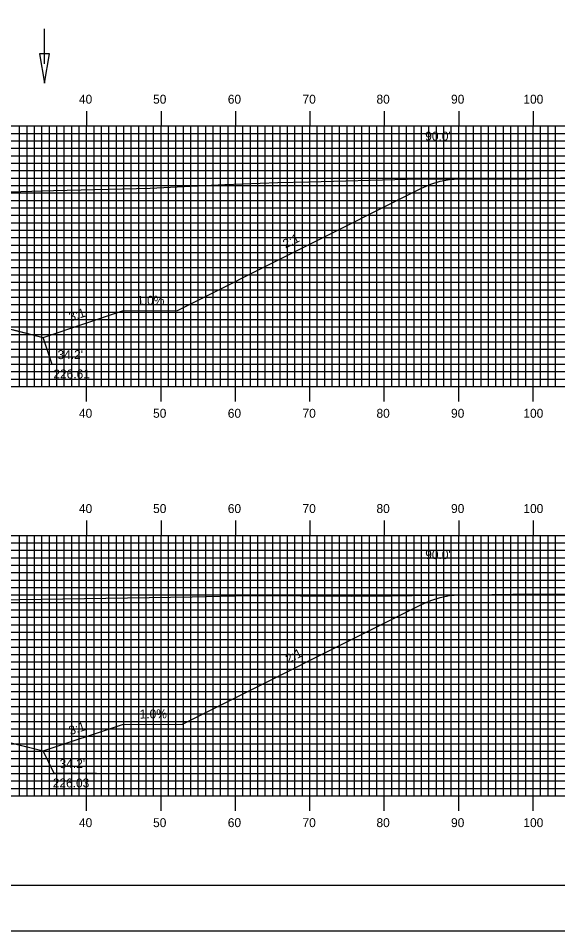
# Model space of a CAD drawing. Extents: x 1817670 to 1818013, y 442591 to 442811.
# Drawn here: x 1817866.4 to 1817938.9, y 442590.5 to 442713.1 of the extents above; entities that cross this region are included whole.
import ezdxf

# ---------------------------------------------------------------- set-up
doc = ezdxf.new("R2010")
doc.units = 0
for name, color, linetype in [('ANNOTATION', 7, 'Continuous'), ('BORDER', 7, 'Continuous'), ('D_Drainage_Ditch_Line', 7, 'Continuous'), ('D_Roadway_Centerline', 7, 'Continuous'), ('D_Roadway_SlopeLines', 7, 'Continuous'), ('D_Text_Standard', 7, 'Continuous'), ('H_V ANNOTATION', 7, 'Continuous'), ('MAJOR', 7, 'Continuous'), ('MINOR', 7, 'Continuous'), ('PLOT BOUNDARY', 7, 'Continuous'), ('S_Roadway_Centerline', 7, 'Continuous')]:
    doc.layers.add(name, color=color, linetype=linetype)

msp = doc.modelspace()

# ---------------------------------------------------------------- linework, layer by layer
at = {"layer": 'ANNOTATION'}
for points in [[(1817876.65, 442666.62), (1817870.96, 442666.62), (1817869.79, 442670.27)], [(1817876.94, 442611.67), (1817871.25, 442611.67), (1817869.79, 442614.7)]]:
    msp.add_lwpolyline(points, dxfattribs=at)
at = {"layer": 'BORDER'}
msp.add_lwpolyline([(1817686.01, 442596.67), (1818006.01, 442596.67), (1818006.01, 442806.67), (1817686.01, 442806.67)], close=True, dxfattribs=at)
at = {"layer": 'D_Drainage_Ditch_Line'}
msp.add_line((1817869.95, 442707.03), (1817869.95, 442711.73), dxfattribs=at)
msp.add_lwpolyline([(1817870.61, 442708.35), (1817869.29, 442708.35), (1817869.95, 442704.41)], close=True, dxfattribs=at)
at = {"layer": 'D_Roadway_Centerline'}
for points in [[(1817745.61, 442681.47), (1817746.86, 442681.54), (1817748.11, 442681.41), (1817749.36, 442681.08), (1817750.61, 442680.56), (1817763.55, 442674.09), (1817790.81, 442673.82), (1817801.44, 442670.27), (1817805.44, 442671.27), (1817815.61, 442673.82), (1817823.61, 442674.14), (1817835.61, 442674.38), (1817847.61, 442674.14), (1817855.61, 442673.82), (1817865.79, 442671.27), (1817869.79, 442670.27), (1817880.42, 442673.82), (1817887.8, 442673.89), (1817920.61, 442690.3), (1817921.86, 442690.85), (1817923.11, 442691.24), (1817924.36, 442691.47), (1817925.61, 442691.56)], [(1817745.61, 442627.29), (1817746.86, 442627.3), (1817748.11, 442627.13), (1817749.36, 442626.77), (1817750.61, 442626.24), (1817766.12, 442618.49), (1817790.81, 442618.24), (1817801.44, 442614.7), (1817805.44, 442615.7), (1817815.61, 442618.24), (1817823.61, 442618.56), (1817835.61, 442618.8), (1817847.61, 442618.56), (1817855.61, 442618.24), (1817865.79, 442615.7), (1817869.79, 442614.7), (1817880.42, 442618.24), (1817888.49, 442618.32), (1817920.61, 442634.38), (1817921.86, 442634.93), (1817923.11, 442635.33), (1817924.36, 442635.58), (1817925.61, 442635.67)]]:
    msp.add_lwpolyline(points, dxfattribs=at)
at = {"layer": 'D_Roadway_SlopeLines'}
for points in [[(1817880.42, 442673.82), (1817887.8, 442673.89), (1817920.61, 442690.3), (1817921.86, 442690.85), (1817923.11, 442691.24), (1817924.36, 442691.47), (1817925.61, 442691.56)], [(1817855.61, 442673.82), (1817869.79, 442670.27)], [(1817869.79, 442670.27), (1817880.42, 442673.82)], [(1817880.42, 442618.24), (1817888.49, 442618.32), (1817920.61, 442634.38), (1817921.86, 442634.93), (1817923.11, 442635.33), (1817924.36, 442635.58), (1817925.61, 442635.67)], [(1817855.61, 442618.24), (1817869.79, 442614.7)], [(1817869.79, 442614.7), (1817880.42, 442618.24)]]:
    msp.add_lwpolyline(points, dxfattribs=at)
at = {"layer": 'MAJOR'}
for p, q in [((1817875.61, 442700.67), (1817875.61, 442698.67)), ((1817885.61, 442700.67), (1817885.61, 442698.67)), ((1817895.61, 442700.67), (1817895.61, 442698.67)), ((1817905.61, 442700.67), (1817905.61, 442698.67)), ((1817915.61, 442700.67), (1817915.61, 442698.67)), ((1817925.61, 442700.67), (1817925.61, 442698.67)), ((1817935.61, 442700.67), (1817935.61, 442698.67)), ((1817695.61, 442698.67), (1817975.61, 442698.67)), ((1817695.61, 442698.67), (1817975.61, 442698.67)), ((1817875.61, 442663.67), (1817875.61, 442698.67)), ((1817885.61, 442663.67), (1817885.61, 442698.67)), ((1817895.61, 442663.67), (1817895.61, 442698.67)), ((1817905.61, 442663.67), (1817905.61, 442698.67)), ((1817915.61, 442663.67), (1817915.61, 442698.67)), ((1817925.61, 442663.67), (1817925.61, 442698.67)), ((1817935.61, 442663.67), (1817935.61, 442698.67)), ((1817695.61, 442693.67), (1817975.61, 442693.67)), ((1817695.61, 442688.67), (1817975.61, 442688.67)), ((1817695.61, 442683.67), (1817975.61, 442683.67)), ((1817695.61, 442678.67), (1817975.61, 442678.67)), ((1817695.61, 442673.67), (1817975.61, 442673.67)), ((1817695.61, 442668.67), (1817975.61, 442668.67)), ((1817695.61, 442663.67), (1817975.61, 442663.67)), ((1817695.61, 442663.67), (1817975.61, 442663.67)), ((1817875.61, 442661.66), (1817875.61, 442663.67)), ((1817885.61, 442661.66), (1817885.61, 442663.67)), ((1817895.61, 442661.66), (1817895.61, 442663.67)), ((1817905.61, 442661.66), (1817905.61, 442663.67)), ((1817915.61, 442661.66), (1817915.61, 442663.67)), ((1817925.61, 442661.66), (1817925.61, 442663.67)), ((1817935.61, 442661.66), (1817935.61, 442663.67)), ((1817875.61, 442645.67), (1817875.61, 442643.67)), ((1817885.61, 442645.67), (1817885.61, 442643.67)), ((1817895.61, 442645.67), (1817895.61, 442643.67)), ((1817905.61, 442645.67), (1817905.61, 442643.67)), ((1817915.61, 442645.67), (1817915.61, 442643.67)), ((1817925.61, 442645.67), (1817925.61, 442643.67)), ((1817935.61, 442645.67), (1817935.61, 442643.67)), ((1817695.61, 442643.67), (1817975.61, 442643.67)), ((1817695.61, 442643.67), (1817975.61, 442643.67)), ((1817875.61, 442608.67), (1817875.61, 442643.67)), ((1817885.61, 442608.67), (1817885.61, 442643.67)), ((1817895.61, 442608.67), (1817895.61, 442643.67)), ((1817905.61, 442608.67), (1817905.61, 442643.67)), ((1817915.61, 442608.67), (1817915.61, 442643.67)), ((1817925.61, 442608.67), (1817925.61, 442643.67)), ((1817935.61, 442608.67), (1817935.61, 442643.67)), ((1817695.61, 442638.67), (1817975.61, 442638.67)), ((1817695.61, 442633.67), (1817975.61, 442633.67)), ((1817695.61, 442628.67), (1817975.61, 442628.67)), ((1817695.61, 442623.67), (1817975.61, 442623.67)), ((1817695.61, 442618.67), (1817975.61, 442618.67)), ((1817695.61, 442613.67), (1817975.61, 442613.67)), ((1817695.61, 442608.67), (1817975.61, 442608.67)), ((1817695.61, 442608.67), (1817975.61, 442608.67)), ((1817875.61, 442606.66), (1817875.61, 442608.67)), ((1817885.61, 442606.66), (1817885.61, 442608.67)), ((1817895.61, 442606.66), (1817895.61, 442608.67)), ((1817905.61, 442606.66), (1817905.61, 442608.67)), ((1817915.61, 442606.66), (1817915.61, 442608.67)), ((1817925.61, 442606.66), (1817925.61, 442608.67)), ((1817935.61, 442606.66), (1817935.61, 442608.67))]:
    msp.add_line(p, q, dxfattribs=at)
at = {"layer": 'MINOR'}
for p, q in [((1817866.61, 442663.67), (1817866.61, 442698.67)), ((1817867.61, 442663.67), (1817867.61, 442698.67)), ((1817868.61, 442663.67), (1817868.61, 442698.67)), ((1817869.61, 442663.67), (1817869.61, 442698.67)), ((1817870.61, 442663.67), (1817870.61, 442698.67)), ((1817871.61, 442663.67), (1817871.61, 442698.67)), ((1817872.61, 442663.67), (1817872.61, 442698.67)), ((1817873.61, 442663.67), (1817873.61, 442698.67)), ((1817874.61, 442663.67), (1817874.61, 442698.67)), ((1817876.61, 442663.67), (1817876.61, 442698.67)), ((1817877.61, 442663.67), (1817877.61, 442698.67)), ((1817878.61, 442663.67), (1817878.61, 442698.67)), ((1817879.61, 442663.67), (1817879.61, 442698.67)), ((1817880.61, 442663.67), (1817880.61, 442698.67)), ((1817881.61, 442663.67), (1817881.61, 442698.67)), ((1817882.61, 442663.67), (1817882.61, 442698.67)), ((1817883.61, 442663.67), (1817883.61, 442698.67)), ((1817884.61, 442663.67), (1817884.61, 442698.67)), ((1817886.61, 442663.67), (1817886.61, 442698.67)), ((1817887.61, 442663.67), (1817887.61, 442698.67)), ((1817888.61, 442663.67), (1817888.61, 442698.67)), ((1817889.61, 442663.67), (1817889.61, 442698.67)), ((1817890.61, 442663.67), (1817890.61, 442698.67)), ((1817891.61, 442663.67), (1817891.61, 442698.67)), ((1817892.61, 442663.67), (1817892.61, 442698.67)), ((1817893.61, 442663.67), (1817893.61, 442698.67)), ((1817894.61, 442663.67), (1817894.61, 442698.67)), ((1817896.61, 442663.67), (1817896.61, 442698.67)), ((1817897.61, 442663.67), (1817897.61, 442698.67)), ((1817898.61, 442663.67), (1817898.61, 442698.67)), ((1817899.61, 442663.67), (1817899.61, 442698.67)), ((1817900.61, 442663.67), (1817900.61, 442698.67)), ((1817901.61, 442663.67), (1817901.61, 442698.67)), ((1817902.61, 442663.67), (1817902.61, 442698.67)), ((1817903.61, 442663.67), (1817903.61, 442698.67)), ((1817904.61, 442663.67), (1817904.61, 442698.67)), ((1817906.61, 442663.67), (1817906.61, 442698.67)), ((1817907.61, 442663.67), (1817907.61, 442698.67)), ((1817908.61, 442663.67), (1817908.61, 442698.67)), ((1817909.61, 442663.67), (1817909.61, 442698.67)), ((1817910.61, 442663.67), (1817910.61, 442698.67)), ((1817911.61, 442663.67), (1817911.61, 442698.67)), ((1817912.61, 442663.67), (1817912.61, 442698.67)), ((1817913.61, 442663.67), (1817913.61, 442698.67)), ((1817914.61, 442663.67), (1817914.61, 442698.67)), ((1817916.61, 442663.67), (1817916.61, 442698.67)), ((1817917.61, 442663.67), (1817917.61, 442698.67)), ((1817918.61, 442663.67), (1817918.61, 442698.67)), ((1817919.61, 442663.67), (1817919.61, 442698.67)), ((1817920.61, 442663.67), (1817920.61, 442698.67)), ((1817921.61, 442663.67), (1817921.61, 442698.67)), ((1817922.61, 442663.67), (1817922.61, 442698.67)), ((1817923.61, 442663.67), (1817923.61, 442698.67)), ((1817924.61, 442663.67), (1817924.61, 442698.67)), ((1817926.61, 442663.67), (1817926.61, 442698.67)), ((1817927.61, 442663.67), (1817927.61, 442698.67)), ((1817928.61, 442663.67), (1817928.61, 442698.67)), ((1817929.61, 442663.67), (1817929.61, 442698.67)), ((1817930.61, 442663.67), (1817930.61, 442698.67)), ((1817931.61, 442663.67), (1817931.61, 442698.67)), ((1817932.61, 442663.67), (1817932.61, 442698.67)), ((1817933.61, 442663.67), (1817933.61, 442698.67)), ((1817934.61, 442663.67), (1817934.61, 442698.67)), ((1817936.61, 442663.67), (1817936.61, 442698.67)), ((1817937.61, 442663.67), (1817937.61, 442698.67)), ((1817938.61, 442663.67), (1817938.61, 442698.67)), ((1817695.61, 442697.67), (1817975.61, 442697.67)), ((1817695.61, 442696.67), (1817975.61, 442696.67)), ((1817695.61, 442695.67), (1817975.61, 442695.67)), ((1817695.61, 442694.67), (1817975.61, 442694.67)), ((1817695.61, 442692.67), (1817975.61, 442692.67)), ((1817695.61, 442691.67), (1817975.61, 442691.67)), ((1817695.61, 442690.67), (1817975.61, 442690.67)), ((1817695.61, 442689.67), (1817975.61, 442689.67)), ((1817695.61, 442687.67), (1817975.61, 442687.67)), ((1817695.61, 442686.67), (1817975.61, 442686.67)), ((1817695.61, 442685.67), (1817975.61, 442685.67)), ((1817695.61, 442684.67), (1817975.61, 442684.67)), ((1817695.61, 442682.67), (1817975.61, 442682.67)), ((1817695.61, 442681.67), (1817975.61, 442681.67)), ((1817695.61, 442680.67), (1817975.61, 442680.67)), ((1817695.61, 442679.67), (1817975.61, 442679.67)), ((1817695.61, 442677.67), (1817975.61, 442677.67)), ((1817695.61, 442676.67), (1817975.61, 442676.67)), ((1817695.61, 442675.67), (1817975.61, 442675.67)), ((1817695.61, 442674.67), (1817975.61, 442674.67)), ((1817695.61, 442672.67), (1817975.61, 442672.67)), ((1817695.61, 442671.67), (1817975.61, 442671.67)), ((1817695.61, 442670.67), (1817975.61, 442670.67)), ((1817695.61, 442669.67), (1817975.61, 442669.67)), ((1817695.61, 442667.67), (1817975.61, 442667.67)), ((1817695.61, 442666.67), (1817975.61, 442666.67)), ((1817695.61, 442665.67), (1817975.61, 442665.67)), ((1817695.61, 442664.67), (1817975.61, 442664.67)), ((1817866.61, 442608.67), (1817866.61, 442643.67)), ((1817867.61, 442608.67), (1817867.61, 442643.67)), ((1817868.61, 442608.67), (1817868.61, 442643.67)), ((1817869.61, 442608.67), (1817869.61, 442643.67)), ((1817870.61, 442608.67), (1817870.61, 442643.67)), ((1817871.61, 442608.67), (1817871.61, 442643.67)), ((1817872.61, 442608.67), (1817872.61, 442643.67)), ((1817873.61, 442608.67), (1817873.61, 442643.67)), ((1817874.61, 442608.67), (1817874.61, 442643.67)), ((1817876.61, 442608.67), (1817876.61, 442643.67)), ((1817877.61, 442608.67), (1817877.61, 442643.67)), ((1817878.61, 442608.67), (1817878.61, 442643.67)), ((1817879.61, 442608.67), (1817879.61, 442643.67)), ((1817880.61, 442608.67), (1817880.61, 442643.67)), ((1817881.61, 442608.67), (1817881.61, 442643.67)), ((1817882.61, 442608.67), (1817882.61, 442643.67)), ((1817883.61, 442608.67), (1817883.61, 442643.67)), ((1817884.61, 442608.67), (1817884.61, 442643.67)), ((1817886.61, 442608.67), (1817886.61, 442643.67)), ((1817887.61, 442608.67), (1817887.61, 442643.67)), ((1817888.61, 442608.67), (1817888.61, 442643.67)), ((1817889.61, 442608.67), (1817889.61, 442643.67)), ((1817890.61, 442608.67), (1817890.61, 442643.67)), ((1817891.61, 442608.67), (1817891.61, 442643.67)), ((1817892.61, 442608.67), (1817892.61, 442643.67)), ((1817893.61, 442608.67), (1817893.61, 442643.67)), ((1817894.61, 442608.67), (1817894.61, 442643.67)), ((1817896.61, 442608.67), (1817896.61, 442643.67)), ((1817897.61, 442608.67), (1817897.61, 442643.67)), ((1817898.61, 442608.67), (1817898.61, 442643.67)), ((1817899.61, 442608.67), (1817899.61, 442643.67)), ((1817900.61, 442608.67), (1817900.61, 442643.67)), ((1817901.61, 442608.67), (1817901.61, 442643.67)), ((1817902.61, 442608.67), (1817902.61, 442643.67)), ((1817903.61, 442608.67), (1817903.61, 442643.67)), ((1817904.61, 442608.67), (1817904.61, 442643.67)), ((1817906.61, 442608.67), (1817906.61, 442643.67)), ((1817907.61, 442608.67), (1817907.61, 442643.67)), ((1817908.61, 442608.67), (1817908.61, 442643.67)), ((1817909.61, 442608.67), (1817909.61, 442643.67)), ((1817910.61, 442608.67), (1817910.61, 442643.67)), ((1817911.61, 442608.67), (1817911.61, 442643.67)), ((1817912.61, 442608.67), (1817912.61, 442643.67)), ((1817913.61, 442608.67), (1817913.61, 442643.67)), ((1817914.61, 442608.67), (1817914.61, 442643.67)), ((1817916.61, 442608.67), (1817916.61, 442643.67)), ((1817917.61, 442608.67), (1817917.61, 442643.67)), ((1817918.61, 442608.67), (1817918.61, 442643.67)), ((1817919.61, 442608.67), (1817919.61, 442643.67)), ((1817920.61, 442608.67), (1817920.61, 442643.67)), ((1817921.61, 442608.67), (1817921.61, 442643.67)), ((1817922.61, 442608.67), (1817922.61, 442643.67)), ((1817923.61, 442608.67), (1817923.61, 442643.67)), ((1817924.61, 442608.67), (1817924.61, 442643.67)), ((1817926.61, 442608.67), (1817926.61, 442643.67)), ((1817927.61, 442608.67), (1817927.61, 442643.67)), ((1817928.61, 442608.67), (1817928.61, 442643.67)), ((1817929.61, 442608.67), (1817929.61, 442643.67)), ((1817930.61, 442608.67), (1817930.61, 442643.67)), ((1817931.61, 442608.67), (1817931.61, 442643.67)), ((1817932.61, 442608.67), (1817932.61, 442643.67)), ((1817933.61, 442608.67), (1817933.61, 442643.67)), ((1817934.61, 442608.67), (1817934.61, 442643.67)), ((1817936.61, 442608.67), (1817936.61, 442643.67)), ((1817937.61, 442608.67), (1817937.61, 442643.67)), ((1817938.61, 442608.67), (1817938.61, 442643.67)), ((1817695.61, 442642.67), (1817975.61, 442642.67)), ((1817695.61, 442641.67), (1817975.61, 442641.67)), ((1817695.61, 442640.67), (1817975.61, 442640.67)), ((1817695.61, 442639.67), (1817975.61, 442639.67)), ((1817695.61, 442637.67), (1817975.61, 442637.67)), ((1817695.61, 442636.67), (1817975.61, 442636.67)), ((1817695.61, 442635.67), (1817975.61, 442635.67)), ((1817695.61, 442634.67), (1817975.61, 442634.67)), ((1817695.61, 442632.67), (1817975.61, 442632.67)), ((1817695.61, 442631.67), (1817975.61, 442631.67)), ((1817695.61, 442630.67), (1817975.61, 442630.67)), ((1817695.61, 442629.67), (1817975.61, 442629.67)), ((1817695.61, 442627.67), (1817975.61, 442627.67)), ((1817695.61, 442626.67), (1817975.61, 442626.67)), ((1817695.61, 442625.67), (1817975.61, 442625.67)), ((1817695.61, 442624.67), (1817975.61, 442624.67)), ((1817695.61, 442622.67), (1817975.61, 442622.67)), ((1817695.61, 442621.67), (1817975.61, 442621.67)), ((1817695.61, 442620.67), (1817975.61, 442620.67)), ((1817695.61, 442619.67), (1817975.61, 442619.67)), ((1817695.61, 442617.67), (1817975.61, 442617.67)), ((1817695.61, 442616.67), (1817975.61, 442616.67)), ((1817695.61, 442615.67), (1817975.61, 442615.67)), ((1817695.61, 442614.67), (1817975.61, 442614.67)), ((1817695.61, 442612.67), (1817975.61, 442612.67)), ((1817695.61, 442611.67), (1817975.61, 442611.67)), ((1817695.61, 442610.67), (1817975.61, 442610.67)), ((1817695.61, 442609.67), (1817975.61, 442609.67))]:
    msp.add_line(p, q, dxfattribs=at)
at = {"layer": 'PLOT BOUNDARY'}
msp.add_lwpolyline([(1817669.83, 442590.55), (1818009.83, 442590.55), (1818009.83, 442810.55), (1817669.83, 442810.55)], close=True, dxfattribs=at)
at = {"layer": 'S_Roadway_Centerline'}
for points in [[(1817864.27, 442689.84), (1817866.79, 442689.88), (1817871.18, 442689.99), (1817884.14, 442690.33), (1817894.17, 442690.79), (1817901.31, 442691.06), (1817905.48, 442691.19), (1817918.69, 442691.51), (1817924.2, 442691.56), (1817935.09, 442691.55), (1817939.27, 442691.69), (1817951.66, 442691.85), (1817959.63, 442691.72), (1817969.2, 442691.61), (1817975.61, 442691.58)], [(1817863.69, 442634.99), (1817889.78, 442635.42), (1817897.45, 442635.6), (1817911.25, 442635.5), (1817914.57, 442635.55), (1817916.52, 442635.54), (1817925.03, 442635.66), (1817930.06, 442635.72), (1817931.11, 442635.74), (1817932.88, 442635.75), (1817948.16, 442635.77), (1817955.38, 442635.61), (1817965.03, 442635.48), (1817975.61, 442635.37)]]:
    msp.add_lwpolyline(points, dxfattribs=at)

# ---------------------------------------------------------------- texts
at = {"layer": 'ANNOTATION'}
for s, rotation, p in [('2:1', 26.5651, (1817902.35, 442682.2)), ('1.0%', 0.5729, (1817882.4, 442674.64)), ('3:1', 18.4349, (1817873.44, 442672.4)), ('2:1', 26.5651, (1817902.7, 442626.46)), ('1.0%', 0.5729, (1817882.74, 442619.06)), ('3:1', 18.4349, (1817873.44, 442616.82))]:
    msp.add_text(s, height=1.2, rotation=rotation, dxfattribs=at).set_placement(p)
for s, p in [("34.2'", (1817871.69, 442667.35)), ('226.61', (1817871.14, 442664.75)), ("34.2'", (1817871.98, 442612.4)), ('226.03', (1817871.06, 442609.8))]:
    msp.add_text(s, height=1.2, dxfattribs=at).set_placement(p)
at = {"layer": 'D_Text_Standard'}
for p in [(1817921.11, 442696.71), (1817921.11, 442640.48)]:
    msp.add_text("90.0'", height=1.2, dxfattribs=at).set_placement(p)
at = {"layer": 'H_V ANNOTATION'}
for s, p in [('40', (1817874.58, 442701.67)), ('50', (1817884.54, 442701.67)), ('60', (1817894.58, 442701.67)), ('70', (1817904.62, 442701.67)), ('80', (1817914.56, 442701.67)), ('90', (1817924.58, 442701.67)), ('100', (1817934.3, 442701.67)), ('40', (1817874.58, 442659.47)), ('50', (1817884.54, 442659.47)), ('60', (1817894.58, 442659.47)), ('70', (1817904.62, 442659.47)), ('80', (1817914.56, 442659.47)), ('90', (1817924.58, 442659.47)), ('100', (1817934.3, 442659.47)), ('40', (1817874.58, 442646.67)), ('50', (1817884.54, 442646.67)), ('60', (1817894.58, 442646.67)), ('70', (1817904.62, 442646.67)), ('80', (1817914.56, 442646.67)), ('90', (1817924.58, 442646.67)), ('100', (1817934.3, 442646.67)), ('40', (1817874.58, 442604.47)), ('50', (1817884.54, 442604.47)), ('60', (1817894.58, 442604.47)), ('70', (1817904.62, 442604.47)), ('80', (1817914.56, 442604.47)), ('90', (1817924.58, 442604.47)), ('100', (1817934.3, 442604.47))]:
    msp.add_text(s, height=1.2, dxfattribs=at).set_placement(p)

doc.saveas('drawing.dxf')
